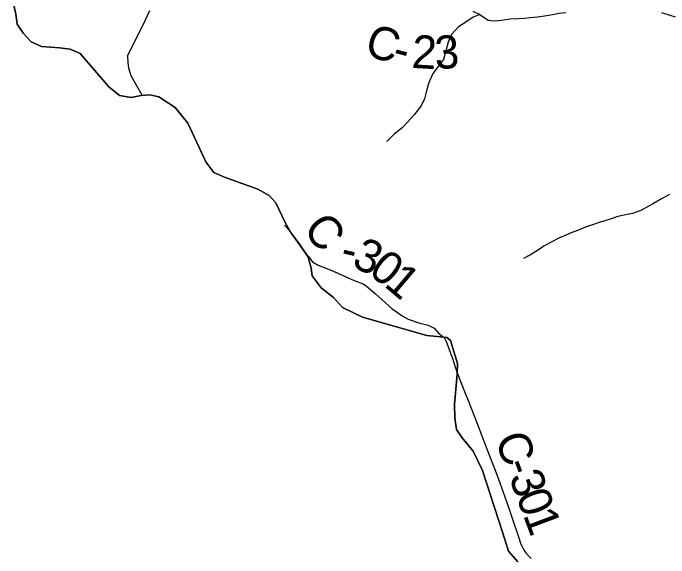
# Model space of a CAD drawing. Extents: x 1578669 to 1989827, y 208020 to 553079.
# Drawn here: x 1740620 to 1746556, y 374035 to 378964 of the extents above; entities that cross this region are included whole.
import ezdxf

# ---------------------------------------------------------------- set-up
doc = ezdxf.new("R2010")
doc.units = 0
for name, color, linetype in [('GM_X_Adjacent_County', 7, 'Continuous'), ('GM_X_County', 7, 'Continuous'), ('GM_X_County_Road', 7, 'Continuous'), ('GM_X_County_Road_Text', 7, 'Continuous'), ('GM_X_Minor_River', 7, 'Continuous'), ('GM_X_Township', 7, 'Continuous')]:
    doc.layers.add(name, color=color, linetype=linetype)

msp = doc.modelspace()

# ---------------------------------------------------------------- linework, layer by layer
at = {"layer": 'GM_X_Adjacent_County'}
msp.add_lwpolyline([(1740620.4, 379063.9), (1740644, 378955.5), (1740657.7, 378865.3), (1740715.5, 378780.8), (1740785.3, 378704.4), (1740877.3, 378661.9), (1741039.6, 378649.2), (1741137.7, 378636.8), (1741227.8, 378598.4), (1741487.1, 378296.6), (1741584.4, 378218.2), (1741690.2, 378202), (1741778.5, 378217.8), (1741857, 378224.7), (1741940.8, 378206.9), (1742087, 378109.7), (1742200.4, 377969), (1742364.1, 377617.5), (1742435.9, 377523), (1742533.9, 377478.5), (1742836.1, 377371), (1742938, 377314.5), (1742999.9, 377248.1), (1743079.4, 377077.3), (1743138.7, 376974.4), (1743212.7, 376872.7), (1743276.7, 376781.3), (1743291.3, 376756.8), (1743318.2, 376655.3), (1743325.9, 376587.1), (1743409.7, 376478.5), (1743519.6, 376389.9), (1743601.4, 376301.3), (1743783.4, 376212.4), (1744365.8, 376047.7), (1744458.1, 376037.7), (1744546.9, 376028), (1744578.5, 376001.3), (1744642.3, 375793.5), (1744640.5, 375703.2), (1744636.9, 375662.7), (1744615.9, 375425.1), (1744617.4, 375298.8), (1744635, 375196.4), (1744684.8, 375120.1), (1744784.6, 375001.4), (1744868, 374826.6), (1745050.2, 374268.5), (1745105.7, 374095.8), (1745189.4, 373999.2)], dxfattribs=at)
at = {"layer": 'GM_X_County'}
msp.add_lwpolyline([(1745189.4, 373999.2), (1745105.7, 374095.8), (1745050.2, 374268.5), (1744868, 374826.6), (1744784.6, 375001.4), (1744684.8, 375120.1), (1744635, 375196.4), (1744617.4, 375298.8), (1744615.9, 375425.1), (1744636.9, 375662.7), (1744640.5, 375703.2), (1744642.3, 375793.5), (1744578.5, 376001.3), (1744546.9, 376028), (1744458.1, 376037.7), (1744365.8, 376047.7), (1743783.4, 376212.4), (1743601.4, 376301.3), (1743519.6, 376389.9), (1743409.7, 376478.5), (1743325.9, 376587.1), (1743318.2, 376655.3), (1743291.3, 376756.8), (1743276.7, 376781.3), (1743212.7, 376872.7), (1743138.7, 376974.4), (1743079.4, 377077.3), (1742999.9, 377248.1), (1742938, 377314.5), (1742836.1, 377371), (1742533.9, 377478.5), (1742435.9, 377523), (1742364.1, 377617.5), (1742200.4, 377969), (1742087, 378109.7), (1741940.8, 378206.9), (1741857, 378224.7), (1741778.5, 378217.8), (1741690.2, 378202), (1741584.4, 378218.2), (1741487.1, 378296.6), (1741227.8, 378598.4), (1741137.7, 378636.8), (1741039.6, 378649.2), (1740877.3, 378661.9), (1740785.3, 378704.4), (1740715.5, 378780.8), (1740657.7, 378865.3), (1740644, 378955.5), (1740620.4, 379063.9)], dxfattribs=at)
at = {"layer": 'GM_X_County_Road'}
for points in [[(1741855.4, 378983.5), (1741795.3, 378854.3), (1741708.7, 378690), (1741655.2, 378578.7), (1741658.3, 378515.5), (1741664.5, 378467.7), (1741684.5, 378400), (1741787.7, 378218.6)], [(1743078.2, 377045.3), (1743111.8, 377005.2), (1743143.7, 376963.7), (1743180.2, 376913.5), (1743235.4, 376832.5), (1743271, 376784.7), (1743286.9, 376768.8)], [(1743286.9, 376768.8), (1743330.5, 376714.5), (1743382.5, 376682.3), (1743459.3, 376652.6), (1743552.2, 376615.5), (1743653.8, 376568.4), (1743708.3, 376546.1), (1743787.6, 376516.3), (1743818.5, 376494.9), (1743898.4, 376426.3), (1744052.7, 376288.4), (1744108.9, 376250.1), (1744140.6, 376225.3), (1744196.3, 376195.5), (1744301.7, 376159.6), (1744376, 376141), (1744433, 376115), (1744471.3, 376069.2), (1744522.2, 376030.7)], [(1744522.2, 376030.7), (1744540, 375992.3), (1744564.5, 375931), (1744583.5, 375879), (1744599.1, 375833.6), (1744612.5, 375791.5), (1744640.8, 375710.3)], [(1744640.8, 375710.3), (1744713.4, 375526.1), (1744747.5, 375439.5), (1744761.6, 375406.4), (1744800.5, 375305.2), (1744903.8, 375037.1), (1744947.8, 374920.8), (1744982.4, 374828.8), (1745025.3, 374715.3), (1745056.7, 374629), (1745086.1, 374545.6), (1745122, 374440.2), (1745140.5, 374384.2), (1745190.5, 374234.9), (1745217.2, 374160.9), (1745230.5, 374130.9), (1745243.2, 374108), (1745259.8, 374083.7), (1745283.1, 374056.2), (1745309.1, 374031.2)]]:
    msp.add_lwpolyline(points, dxfattribs=at)
at = {"layer": 'GM_X_Minor_River'}
for points in [[(1744843.6, 378952.4), (1744785.5, 378926.7), (1744717.2, 378881), (1744650.9, 378839.3), (1744588.5, 378769.6), (1744558.1, 378701.7), (1744537.6, 378621.7), (1744517.1, 378545.7), (1744458.7, 378469.9), (1744420.3, 378418), (1744379.8, 378326.1), (1744359.3, 378250.2), (1744343, 378188.2), (1744314.6, 378124.2), (1744252.1, 378044.5), (1744189.7, 377978.7), (1744141.4, 377926.9), (1744071, 377869.2), (1744002.6, 377803.5)], [(1744781.8, 378982.8), (1744843.6, 378952.4), (1744921.3, 378901.9), (1744975.3, 378895.6), (1745041.4, 378899.2), (1745119.5, 378912.8), (1745195.5, 378914.4), (1745249.5, 378918.1), (1745301.6, 378923.8), (1745365.6, 378931.5), (1745431.7, 378941.1), (1745501.8, 378952.7), (1745561.9, 378962.4), (1745622, 378970.1)], [(1746488.2, 378971.2), (1746556.1, 378948.8)], [(1746556.1, 378948.8), (1746614, 378930.5)], [(1746562.5, 377324.5), (1746488.2, 377284.9), (1746416, 377241.2), (1746363.8, 377211.5), (1746301.5, 377177.8), (1746227.4, 377150.2), (1746177.3, 377142.5), (1746095.2, 377122.9), (1746035, 377103.2), (1745976.9, 377085.5), (1745924.8, 377069.8), (1745856.6, 377046.1), (1745800.5, 377026.4), (1745728.3, 376996.8), (1745672.2, 376975), (1745622, 376955.3), (1745565.9, 376931.6), (1745485.6, 376890), (1745425.4, 376854.3), (1745375.2, 376822.5), (1745304.9, 376776.8), (1745240.7, 376745.1)]]:
    msp.add_lwpolyline(points, dxfattribs=at)
at = {"layer": 'GM_X_Township'}
msp.add_lwpolyline([(1745189.4, 373999.2), (1745105.7, 374095.8), (1745050.2, 374268.5), (1744868, 374826.6), (1744784.6, 375001.4), (1744684.8, 375120.1), (1744635, 375196.4), (1744617.4, 375298.8), (1744615.9, 375425.1), (1744636.9, 375662.7), (1744640.5, 375703.2), (1744642.3, 375793.5), (1744578.5, 376001.3), (1744546.9, 376028), (1744458.1, 376037.7), (1744365.8, 376047.7), (1743783.4, 376212.4), (1743601.4, 376301.3), (1743519.6, 376389.9), (1743409.7, 376478.5), (1743325.9, 376587.1), (1743318.2, 376655.3), (1743291.3, 376756.8), (1743276.7, 376781.3), (1743212.7, 376872.7), (1743138.7, 376974.4), (1743079.4, 377077.3), (1742999.9, 377248.1), (1742938, 377314.5), (1742836.1, 377371), (1742533.9, 377478.5), (1742435.9, 377523), (1742364.1, 377617.5), (1742200.4, 377969), (1742087, 378109.7), (1741940.8, 378206.9), (1741857, 378224.7), (1741778.5, 378217.8), (1741690.2, 378202), (1741584.4, 378218.2), (1741487.1, 378296.6), (1741227.8, 378598.4), (1741137.7, 378636.8), (1741039.6, 378649.2), (1740877.3, 378661.9), (1740785.3, 378704.4), (1740715.5, 378780.8), (1740657.7, 378865.3), (1740644, 378955.5), (1740620.4, 379063.9)], dxfattribs=at)

# ---------------------------------------------------------------- texts
at = {"layer": 'GM_X_County_Road_Text'}
for s, rotation, p in [('C', 342.07973, (1743788.1, 378591.5)), ('2', 356.61405, (1744223.2, 378469.3)), ('3', 2.45903, (1744441.1, 378458.1)), ('-', 345.36553, (1744040.6, 378510.4)), ('C', 307.66565, (1743235.8, 377009.9)), ('3', 335.95442, (1743675, 376674.6)), ('-', 346.91532, (1743570.5, 376697.4)), ('0', 322.36283, (1743826.3, 376609.5)), ('1', 319.7705, (1743968.7, 376499.8)), ('C', 290.4054, (1744978, 375112.7)), ('-', 290.4054, (1745063.3, 374883.5)), ('3', 290.40539, (1745105.8, 374769)), ('0', 290.40858, (1745169.8, 374597.2)), ('1', 290.4491, (1745233.8, 374425.1))]:
    msp.add_text(s, height=300, rotation=rotation, dxfattribs=at).set_placement(p)

doc.saveas('drawing.dxf')
